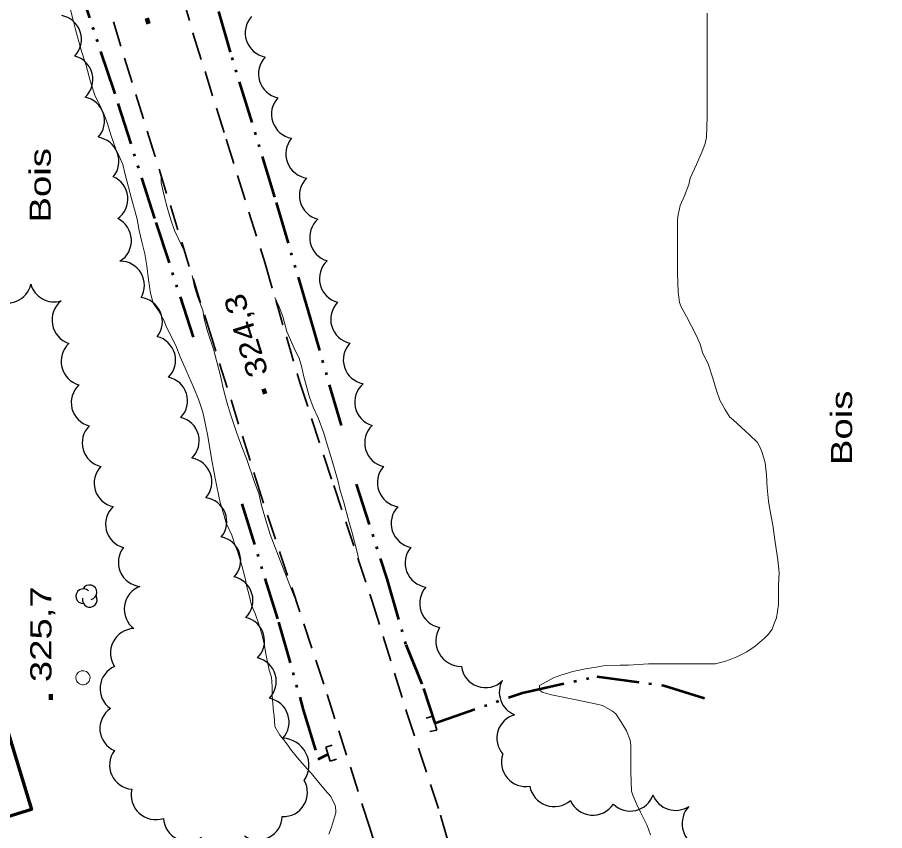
# Model space of a CAD drawing. Extents: x 240591 to 242335, y 5323482 to 5326937.
# Drawn here: x 241235.7 to 241358.3, y 5325156.7 to 5325271.7 of the extents above; entities that cross this region are included whole.
import ezdxf

# ---------------------------------------------------------------- set-up
doc = ezdxf.new("R2010")
doc.units = 0
doc.header["$LTSCALE"] = 1.2
for name, pattern in [('DASH_DOUBLE_DOT', [9.2, 5, -1.2, 0.3, -1.2, 0.3, -1.2]), ('LONG_DASHED', [7.5, 6, -1.5]), ('MEDIUM_DASHED', [4.5, 3, -1.5])]:
    doc.linetypes.add(name, pattern=pattern)
for name, color, linetype, lineweight in [('2', 7, 'Continuous', 13), ('21', 7, 'Continuous', 53), ('26', 7, 'Continuous', 35), ('3', 7, 'Continuous', 140), ('31', 7, 'Continuous', 70), ('36', 7, 'Continuous', 13), ('4', 7, 'DASH_DOUBLE_DOT', 53), ('44', 7, 'Continuous', 25)]:
    doc.layers.add(name, color=color, linetype=linetype, lineweight=lineweight)

msp = doc.modelspace()

# ---------------------------------------------------------------- linework, layer by layer
at = {"layer": '2'}
msp.add_line((241272, 5325173), (241271.9, 5325173.5), dxfattribs=at)
for points in [[(241243.2, 5325272.8), (241243.5, 5325271.5), (241243.9, 5325270), (241244.7, 5325267.1), (241245.4, 5325264.9), (241246, 5325262.6), (241246.7, 5325260.6), (241247.3, 5325259.4), (241247.9, 5325258.1), (241248.4, 5325256.7), (241248.9, 5325255.1), (241249.6, 5325253.1), (241250.1, 5325252), (241250.6, 5325250.9), (241250.9, 5325249.5), (241251.4, 5325247.7), (241251.8, 5325246.1), (241252.6, 5325243.2), (241252.9, 5325241.6), (241253.3, 5325240), (241253.7, 5325238.3), (241254, 5325236.6), (241254.2, 5325234.6), (241254.5, 5325232.7), (241254.9, 5325231.3), (241255.6, 5325230.3), (241256.4, 5325228.9), (241256.8, 5325227.8), (241258.1, 5325225.3), (241258.7, 5325223.7), (241259.6, 5325221.7), (241260.6, 5325219.4), (241261.3, 5325217.7), (241261.9, 5325215.9), (241262.3, 5325214.1), (241262.6, 5325212.5), (241263, 5325210.2), (241263.2, 5325208.8), (241263.7, 5325206.3), (241264.3, 5325203.3), (241264.9, 5325201.2), (241265.2, 5325200.2), (241266, 5325198.5), (241266.5, 5325196.9), (241266.8, 5325196.2)], [(241259.3, 5325238.6), (241258.9, 5325239.5), (241257.9, 5325241.6), (241257.4, 5325243.1), (241256.9, 5325244.7), (241256.5, 5325246.3), (241256, 5325248.3), (241256, 5325249.1)], [(241274.8, 5325189.8), (241273.5, 5325193.2), (241272.6, 5325195.5), (241271.4, 5325198.6), (241270.9, 5325200.3), (241270.2, 5325202.7), (241269.8, 5325204.4), (241269.2, 5325206), (241268.1, 5325209.2), (241267.4, 5325211), (241266.7, 5325212.9), (241265.8, 5325215.6), (241265.3, 5325217.3), (241264.8, 5325219.1), (241264.4, 5325221), (241263.9, 5325223), (241263.4, 5325224.8), (241262.5, 5325227.5), (241262.1, 5325229.1), (241261.9, 5325230.3), (241261.7, 5325230.8), (241261.2, 5325232.1), (241260.7, 5325233.6), (241260.4, 5325235.2)], [(241272.1, 5325232.1), (241272.7, 5325230.8), (241273.2, 5325229.4), (241273.8, 5325227.3)], [(241273.8, 5325227.3), (241275, 5325224.5), (241275.5, 5325223.5), (241275.9, 5325222.2), (241276.2, 5325220.9), (241277, 5325218), (241277.5, 5325216.6), (241278.2, 5325215.1), (241279, 5325212.9), (241279.5, 5325211.3), (241280.2, 5325209), (241281, 5325206.2), (241281.3, 5325204.8), (241281.8, 5325203.3), (241282.6, 5325200.3), (241283, 5325198.8), (241283.7, 5325196.1), (241284.2, 5325193.9)], [(241266.8, 5325196.2), (241267.4, 5325194.2), (241267.9, 5325192.4), (241268.1, 5325191.2), (241268.4, 5325190.2), (241268.8, 5325188.6), (241269.3, 5325187.4), (241269.9, 5325185.6), (241270.3, 5325184.3), (241270.6, 5325182.9), (241270.8, 5325181.7), (241271.3, 5325179.4), (241271.6, 5325178.4), (241271.7, 5325177.1), (241271.7, 5325175.8), (241271.9, 5325173.5)], [(241333.2, 5325180.3), (241330.2, 5325180.3), (241327.6, 5325180.3), (241324.9, 5325180.3), (241323.5, 5325180.2), (241322.1, 5325180.1), (241320.9, 5325180.1), (241318.5, 5325180), (241317.5, 5325179.8), (241316, 5325179.6), (241314.2, 5325179.2), (241312.5, 5325178.7), (241311.5, 5325178.3), (241309.5, 5325177.2), (241309.5, 5325176.6), (241309.9, 5325176.3), (241310.5, 5325176.1), (241311.2, 5325175.9), (241314.7, 5325175.2), (241317.6, 5325174.6), (241318.4, 5325174.4), (241319.8, 5325173.6), (241320.3, 5325173.2), (241321.1, 5325172), (241321.8, 5325170.8), (241322.3, 5325169.5), (241322.4, 5325168.8), (241322.4, 5325167.6), (241322.4, 5325165), (241322.5, 5325162.3), (241322.7, 5325161.7), (241323.2, 5325160.5), (241323.8, 5325159.3), (241324.7, 5325157.4), (241325.2, 5325156.1)], [(241272, 5325173), (241272.1, 5325171.4), (241272.8, 5325170.2), (241273.3, 5325169.6), (241273.9, 5325168.8), (241274.3, 5325168.2), (241275.3, 5325167), (241275.9, 5325166.3), (241276.7, 5325165.4), (241277.2, 5325164.8), (241278.3, 5325163.5), (241279.2, 5325162.4), (241280, 5325161.5), (241280.3, 5325160.9), (241280.6, 5325160.3), (241280.7, 5325159.6), (241280.7, 5325159.2), (241280.5, 5325158.6), (241280.1, 5325157.2), (241279.7, 5325156.2)]]:
    msp.add_lwpolyline(points, dxfattribs=at)
at = {"layer": '2', "linetype": 'LONG_DASHED'}
msp.add_lwpolyline([(241333.2, 5325272.3), (241333.2, 5325269.7), (241333.2, 5325266.6), (241333.2, 5325263.5), (241333.2, 5325260.6), (241333.2, 5325257.7), (241333.1, 5325254.8), (241332.9, 5325253.9), (241332.6, 5325253), (241331.7, 5325250.9), (241330.8, 5325249), (241330.6, 5325248.1), (241330, 5325246.5), (241329.4, 5325245.1), (241329.1, 5325243.8), (241329, 5325243.1), (241329, 5325241.1), (241329, 5325238.1), (241329, 5325235.5), (241329.1, 5325232.9), (241329.3, 5325231.4), (241329.6, 5325230.7), (241330.3, 5325229.4), (241331.7, 5325226.7), (241332.2, 5325225.5), (241332.6, 5325224.2), (241333.1, 5325223.2), (241333.4, 5325222.6), (241334, 5325220.7), (241334.5, 5325219.1), (241335, 5325217.6), (241335.7, 5325216.3), (241336.4, 5325215.2), (241336.9, 5325214.8), (241339.2, 5325212.7), (241340.3, 5325211.6), (241340.7, 5325210.9), (241341, 5325210.2), (241341.4, 5325208.7), (241341.6, 5325207), (241341.7, 5325205.2), (241341.9, 5325203.3), (241342, 5325202.4), (241342.5, 5325199.9), (241342.8, 5325197.5), (241343.2, 5325195), (241343.4, 5325193.2), (241343.3, 5325191.4), (241343.3, 5325188.7), (241343, 5325186.8), (241342.7, 5325186), (241342.4, 5325185.2), (241341.9, 5325184.5), (241341.3, 5325183.9), (241340, 5325182.8), (241338.8, 5325182), (241337.4, 5325181.3), (241336, 5325180.7), (241334.4, 5325180.3), (241333.6, 5325180.3), (241333.2, 5325180.3)], dxfattribs=at)
at = {"layer": '21', "linetype": 'MEDIUM_DASHED', "lineweight": 35}
for points in [[(241256, 5325285.1), (241260.6, 5325269.2), (241265.2, 5325254.5), (241270.7, 5325236.9), (241275.6, 5325220.1), (241280.4, 5325205.5), (241285.8, 5325189.3), (241290.7, 5325173.5), (241295.5, 5325158.9), (241300.3, 5325142.5), (241303.7, 5325131.5), (241307.4, 5325120), (241310.7, 5325111.7), (241314.2, 5325104.8), (241318, 5325098.9), (241322.8, 5325092.9), (241329.6, 5325086.9), (241336.4, 5325081.7), (241348.1, 5325074.6), (241358.3, 5325068.2)], [(241337.8, 5325069.5), (241324.6, 5325077.8), (241319.1, 5325083.1), (241315.5, 5325086.2), (241308.5, 5325093.3), (241304.3, 5325100.7), (241299.7, 5325111.1), (241296.2, 5325122.7), (241291.2, 5325139.2), (241285.5, 5325157.1), (241279, 5325177.4), (241270.2, 5325203.9), (241263.2, 5325226.2), (241255.1, 5325252.2), (241248.2, 5325274.5)]]:
    msp.add_lwpolyline(points, dxfattribs=at)
at = {"layer": '26'}
for p, q in [((241294.4, 5325172.9), (241293.5, 5325172.6)), ((241294.4, 5325172.9), (241295, 5325170.9)), ((241295, 5325170.9), (241294, 5325170.7)), ((241279.3, 5325168.5), (241280.2, 5325168.8)), ((241279.9, 5325166.5), (241279.3, 5325168.5)), ((241279.9, 5325166.5), (241280.8, 5325166.8))]:
    msp.add_line(p, q, dxfattribs=at)
at = {"layer": '3'}
for p, q in [((241254.2, 5325270.8), (241254, 5325271.6)), ((241270.7, 5325218.5), (241270.5, 5325219.2)), ((241240.4, 5325175.2), (241240.4, 5325176))]:
    msp.add_line(p, q, dxfattribs=at)
at = {"layer": '31'}
msp.add_lwpolyline([(241229.3, 5325157.1), (241225.5, 5325169.6), (241233.9, 5325172.1), (241237.7, 5325159.7)], close=True, dxfattribs=at)
at = {"layer": '36'}
msp.add_ellipse((241244.953, 5325178.32), major_axis=(0.261, -0.965), ratio=0.99964, dxfattribs=at)
at = {"layer": '4'}
for points in [[(241260.6, 5325226.5), (241255.1, 5325243.3), (241249.4, 5325261.2), (241243.4, 5325279.2), (241239.1, 5325294.8), (241237.8, 5325304.3), (241236.7, 5325312.2), (241236.2, 5325316.6)], [(241281.5, 5325214), (241277.1, 5325229.2), (241272.1, 5325246.3), (241265.8, 5325266.8), (241261.1, 5325283.3), (241257, 5325299.7), (241254.8, 5325311.2), (241254.5, 5325316.6)], [(241283.6, 5325205.7), (241287.9, 5325192.3), (241290.6, 5325183), (241293.1, 5325176.8), (241294.7, 5325171.9)], [(241267.4, 5325202.9), (241272.6, 5325186.2), (241276.1, 5325173.8), (241278.2, 5325166.8), (241279.6, 5325167.5)], [(241294.7, 5325171.9), (241307.1, 5325176.2), (241317.6, 5325178.5), (241327.1, 5325177.2), (241333.6, 5325175.2)]]:
    msp.add_lwpolyline(points, dxfattribs=at)
at = {"layer": '44'}
for centre, radius, start, end in [((241247.91, 5325246.037), 3.399, 305.20913, 67.15194), ((241285.216, 5325223.302), 3.456, 137.20049, 258.88908), ((241286.82, 5325217.314), 3.449, 131.15878, 253.32238), ((241253.375, 5325194.638), 3.418, 142.04523, 263.87334), ((241265.577, 5325189.248), 3.409, 315.30268, 77.06381), ((241252.274, 5325181.837), 3.436, 92.07369, 214.11412), ((241250.784, 5325176.768), 3.421, 113.31484, 235.16864), ((241250.764, 5325171.141), 3.419, 124.44483, 246.30858), ((241259.764, 5325158.596), 3.428, 182.77089, 304.78261)]:
    msp.add_arc(centre, radius, start, end, dxfattribs=at)
for centre, major_axis, ratio, start_param, end_param in [((241241.292, 5325268.611), (3.277, 1.06), 0.999994, 5.2192212, 7.3460993), ((241271.339, 5325269.524), (-3.269, -1.106), 0.999951, 5.2173984, 7.347417), ((241242.906, 5325262.94), (3.342, 0.848), 0.997329, 5.2162854, 7.3408337), ((241273.218, 5325263.735), (3.378, -0.75), 0.999984, 2.5958887, 4.7217511), ((241244.599, 5325257.09), (3.241, 1.051), 0.999046, 5.2192534, 7.3453037), ((241275.064, 5325258.031), (-3.274, -1.111), 0.999995, 5.2208197, 7.345327), ((241246.607, 5325251.377), (3.32, 0.855), 0.999683, 5.3314507, 7.4607372), ((241277.106, 5325252.423), (-3.272, -1.155), 0.99644, 5.2507931, 7.369505), ((241279.004, 5325246.527), (-3.332, -0.913), 0.997806, 5.2150713, 7.3433219), ((241248.355, 5325240.161), (3.445, 0.175), 0.999978, 5.2224548, 7.3485203), ((241280.473, 5325240.6), (-3.41, -0.618), 0.997465, 5.2605122, 7.3812883), ((241250.232, 5325233.83), (2.958, 1.699), 0.999639, 5.2230719, 7.3452881), ((241281.836, 5325234.778), (-3.428, -0.404), 0.999764, 5.3503078, 7.4802293), ((241234.275, 5325234.739), (3.368, 0.503), 0.999893, 3.9845804, 5.9120951), ((241240.868, 5325234.884), (-3.155, -1.286), 0.998423, 6.1635551, 7.7630325), ((241252.764, 5325228.691), (3.342, 0.693), 0.999882, 5.4042561, 7.5332057), ((241244.091, 5325228.911), (-3.516, -0.096), 0.999836, 5.3719801, 7.4994171), ((241283.435, 5325229.025), (-3.315, -0.985), 0.999995, 5.2212578, 7.3451216), ((241254.643, 5325223.248), (3.277, 0.924), 0.999977, 5.2188454, 7.345817), ((241245.303, 5325223.063), (-3.343, -0.811), 0.999445, 5.2236263, 7.3444008), ((241256.331, 5325217.493), (3.26, 1.005), 0.999949, 5.2227055, 7.3453657), ((241246.729, 5325217.25), (-3.402, -0.449), 0.999682, 5.3353828, 7.4577007), ((241257.976, 5325211.83), (3.295, 0.887), 0.99964, 5.223049, 7.3471851), ((241248.253, 5325211.542), (-3.273, -0.954), 0.999994, 5.2192806, 7.3444032), ((241288.249, 5325211.546), (-3.33, -0.912), 0.999995, 5.2210675, 7.350099), ((241259.775, 5325206.034), (3.213, 1.142), 0.998893, 5.2181694, 7.3402725), ((241249.942, 5325205.852), (-3.261, -0.993), 0.99991, 5.2194607, 7.3451364), ((241290.037, 5325205.914), (-3.301, -1.034), 0.997692, 5.2591391, 7.3834102), ((241261.876, 5325200.399), (-2.686, 2.104), 0.999995, 3.1171546, 5.2432686), ((241251.556, 5325200.036), (2.397, -2.426), 0.999995, 3.1170206, 5.2440652), ((241291.989, 5325200.148), (-3.344, -0.905), 0.998319, 5.2669608, 7.3871634), ((241263.853, 5325194.892), (3.359, 0.543), 0.999825, 5.3718205, 7.4992473), ((241293.93, 5325194.556), (-3.384, -0.618), 0.999884, 5.4067129, 7.5333158), ((241244.993, 5325189.845), (0.273, -1.01), 0.99964, 2.1062282, 6.0452372), ((241245.877, 5325190.394), (0.273, -1.01), 0.99964, 6.2627962, 10.2326713), ((241254.231, 5325188.017), (-3.411, 0.494), 0.999951, 5.2184447, 7.3495572), ((241296.024, 5325188.833), (-3.28, -1.136), 0.997109, 5.215829, 7.3347286), ((241245.907, 5325189.348), (0.273, -1.01), 0.99964, 4.2498678, 8.1364431), ((241267.219, 5325183.531), (3.407, 0.124), 0.999927, 5.4612031, 7.5865017), ((241298.447, 5325183.535), (-3.241, -1.584), 0.998939, 5.2745756, 7.4006995), ((241268.878, 5325177.793), (3.395, 0.341), 0.999882, 5.409807, 7.5317024), ((241301.857, 5325180.358), (3.201, -1.245), 0.998747, 3.6379819, 5.8593478), ((241307.251, 5325176.275), (1.297, -3.187), 0.99696, 3.8241488, 5.5150725), ((241270.688, 5325172.062), (3.407, -0.018), 0.999961, 5.546894, 7.672714), ((241306.904, 5325169.787), (-1.365, -3.15), 0.998461, 3.8240309, 5.837078), ((241273.061, 5325165.925), (3.42, 1.744), 0.99964, 5.2215421, 7.3462817), ((241252.172, 5325165.98), (-3.133, -1.469), 0.993631, 5.2118111, 7.330742), ((241307.534, 5325166.366), (0.298, -3.417), 0.996722, 4.2772039, 6.3739859), ((241273.26, 5325162.109), (2.865, -1.897), 0.997878, 5.2614531, 7.3813986), ((241255.252, 5325161.735), (-2.798, -2.067), 0.999886, 5.410252, 7.5357286), ((241311.569, 5325163.564), (-1.169, -3.274), 0.999913, 5.2213409, 7.345916), ((241317.049, 5325162.387), (-0.512, -3.462), 0.999019, 5.2822535, 7.4038156), ((241322.321, 5325162.882), (-0.402, -3.401), 0.999894, 5.6321738, 7.6340329), ((241328.73, 5325162.975), (0.169, -3.413), 0.998351, 5.0309866, 6.8185197), ((241333.24, 5325157.687), (-3.542, 0.54), 0.999934, 5.6863164, 7.582715), ((241269.707, 5325158.81), (1.568, -3.058), 0.999645, 5.2170492, 7.3424583)]:
    msp.add_ellipse(centre, major_axis=major_axis, ratio=ratio, start_param=start_param, end_param=end_param, dxfattribs=at)

# ---------------------------------------------------------------- texts
at = {"layer": '3'}
for s, height, rotation, width, p in [('324,3', 2.999, 107.112, 1.2, (241271.2, 5325221.4)), ('325,7', 3, 90, 1.35, (241240.5, 5325177.7))]:
    msp.add_text(s, height=height, rotation=rotation, dxfattribs=dict(at, width=width)).set_placement(p)
at = {"layer": '44', "width": 1.35}
for p in [(241240.4, 5325242.7), (241353.7, 5325208.4)]:
    msp.add_text('Bois', height=3, rotation=90, dxfattribs=at).set_placement(p)

doc.saveas('drawing.dxf')
